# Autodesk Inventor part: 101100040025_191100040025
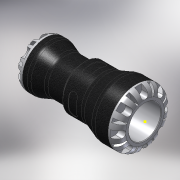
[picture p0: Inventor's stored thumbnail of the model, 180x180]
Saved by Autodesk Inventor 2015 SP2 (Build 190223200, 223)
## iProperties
Created: 2016-12
Part Number: 101100040025_191100040025
Material: PVC-Piping
Description: PLASSON REDUCING COUPLING 40X25 SERIES 1
Document SubType Name: Modeling
Designer: KIM
Mass: 309.689 g
Surface Area: 488.063 cm^2
Volume: 221.206 cm^3
Density: 1.4 g/cm^3
Appearance: Black Cast
Author: KIM
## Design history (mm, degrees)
derived "1011.ipt"
feature "Solid1::1011.ipt"
tag "TaggingFeature1"
body "Solid1"
other parameters: "d0" = 137, "d2" = 29.82, "d5" = 48, "d6" = 71, "d7" = 3.33333, "d8" = 58, "d9" = 25, "d10" = 31.25, "d11" = 21.42, "d12" = 51, "d13" = 2.08333, "d14" = 56, "d15" = 46.4, "d16" = 20 deg, "d17" = 20 deg, "d18" = 130 deg, "d22" = 8.8, "d25" = 8.8, "d26" = 0, "d28" = 360 deg, "d30" = 8 deg, "d31" = 0.8, "d32" = 8 deg, "d33" = 0.8, "d35" = 0, "d37" = 360 deg, "d39" = 10.7, "d42" = 10.7, "d43" = 0, "d45" = 360 deg, "d47" = 0.5, "d48" = 8 deg, "d49" = 8 deg, "d50" = 0.5, "d52" = 0, "d54" = 360 deg, "d56" = 11.6, "d57" = 14, "d58" = 0.5, "d60" = 8.4, "d62" = 14.4, "d63" = 0, "d66" = 0, "d68" = 360 deg, "d75" = 11.35912, "d77" = 54.6, "d78" = 0.7, "d1" = 25, "H_" = 137, "l_" = 71, "E1" = 58, "l1" = 51, "Plasson" = 1, "d20" = 13.375, "d21" = 11, "d24" = 48, "d40" = 58, "d41" = 31.25, "d59" = 22.71825
